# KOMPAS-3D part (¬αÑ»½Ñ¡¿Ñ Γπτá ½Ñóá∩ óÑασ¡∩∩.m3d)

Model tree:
1. Эскиз:1
2. Операция выдавливания:1
     Расстояние 1 = 2
3. Эскиз:2
4. Операция выдавливания:2
     Расстояние 1 = 11
5. Эскиз:3
6. Вырезать элемент выдавливания:1
     Расстояние 1 = 13
7. Эскиз:4
8. Вырезать элемент выдавливания:2
     Расстояние 1 = 4.00309
9. Скругление:1
     Радиус = 0.2
10. Скругление:2
     Радиус = 0.2
11. Эскиз:5
12. Операция выдавливания:3
     Расстояние 1 = 2.5
13. Эскиз:6
14. Операция выдавливания:4
     Расстояние 1 = 0.5
15. Эскиз:7
16. Операция выдавливания:5
     Расстояние 1 = 0.5
17. Эскиз:8
18. Операция выдавливания:6
     Расстояние 1 = 0.5
19. Скругление:3
     Радиус = 0.2
20. Эскиз:9
21. Операция выдавливания:7
     Расстояние 1 = 1
22. Эскиз:10
23. Операция выдавливания:8
     Расстояние 1 = 1

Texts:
  крепление туча левая верхняя
  Сплав АЛ8  ГОСТ 1583-93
